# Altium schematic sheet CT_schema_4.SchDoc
size 294 x 169 mm
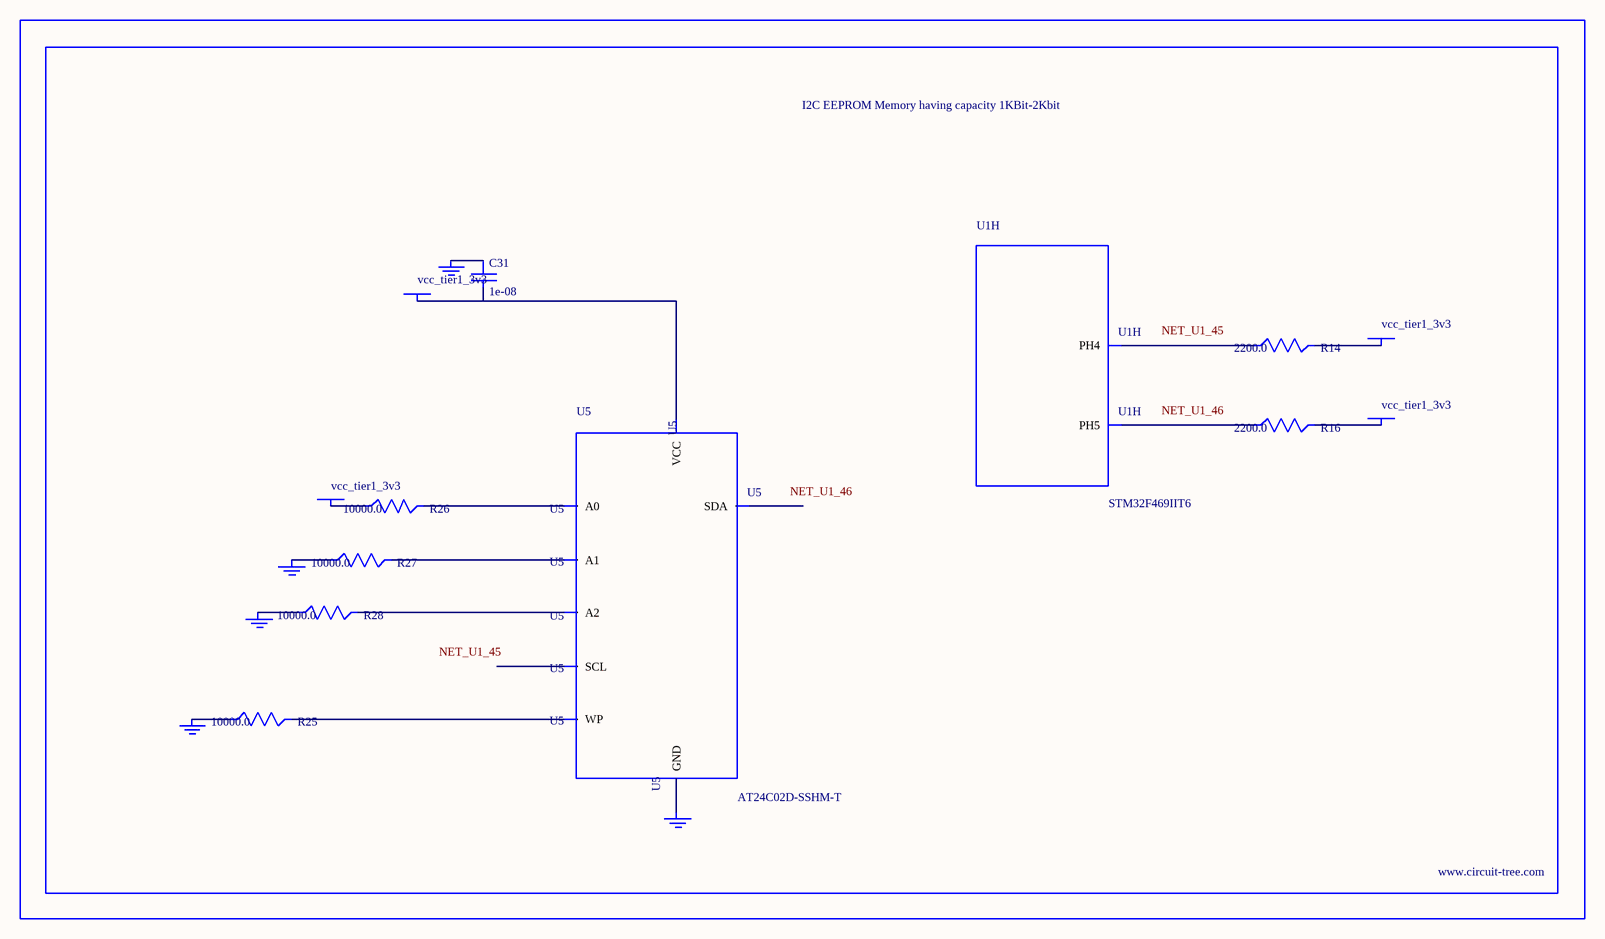
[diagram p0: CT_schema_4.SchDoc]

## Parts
BORDER3  (no value)
C31  1e-08  [C0402]
GND_INSTANCE_3_0  (no value)
GND_INSTANCE_3_1  (no value)
GND_INSTANCE_3_2  (no value)
GND_INSTANCE_3_3  (no value)
GND_INSTANCE_3_4  (no value)
POWER_INSTANCE_3_0  vcc_tier1_3v3
POWER_INSTANCE_3_1  vcc_tier1_3v3
POWER_INSTANCE_3_2  vcc_tier1_3v3
POWER_INSTANCE_3_3  vcc_tier1_3v3
R14  2200.0  [R0603]
R16  2200.0  [R0603]
R25  10000.0  [R0603]
R26  10000.0  [R0603]
R27  10000.0  [R0603]
R28  10000.0  [R0603]
U1  STM32F469IIT6  [LQFP176]  (part H of 14)
U5  AT24C02D-SSHM-T  [AT24C02D]

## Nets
NetC31_1: C31.1 GND_INSTANCE_3_3.0(GND)
NetC31_2: C31.2 POWER_INSTANCE_3_1.0(PWR) U5.8(VCC)
NetGND_INSTANCE_3_0_0: GND_INSTANCE_3_0.0(GND) R27.1
NetGND_INSTANCE_3_1_0: GND_INSTANCE_3_1.0(GND) R28.1
NetGND_INSTANCE_3_2_0: GND_INSTANCE_3_2.0(GND) R25.1
NetGND_INSTANCE_3_4_0: GND_INSTANCE_3_4.0(GND) U5.4(GND)
NetPOWER_INSTANCE_3_0_0: POWER_INSTANCE_3_0.0(PWR) R26.1
NetPOWER_INSTANCE_3_2_0: POWER_INSTANCE_3_2.0(PWR) R14.2
NetPOWER_INSTANCE_3_3_0: POWER_INSTANCE_3_3.0(PWR) R16.2
NetR14_1: R14.1 U1.45(PH4)
NetR16_1: R16.1 U1.46(PH5)
NetR25_2: R25.2 U5.7(WP)
NetR26_2: R26.2 U5.1(A0)
NetR27_2: R27.2 U5.2(A1)
NetR28_2: R28.2 U5.3(A2)

Not connected (* = marked no-connect by the designer): U5 5(SDA) 6(SCL)

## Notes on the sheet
- Labels drawn without touching a wire or pin: NET_U1_45, NET_U1_46

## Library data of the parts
BORDER3 = BORDER_PAGE3
C31 = C0402C103K3RAC
GND_INSTANCE_3_0-GND_INSTANCE_3_4 = GND
POWER_INSTANCE_3_0-POWER_INSTANCE_3_3 = PWR
R14 R16 = RC0603JR-072K2L
R25-R28 = RC0603JR-0710KL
